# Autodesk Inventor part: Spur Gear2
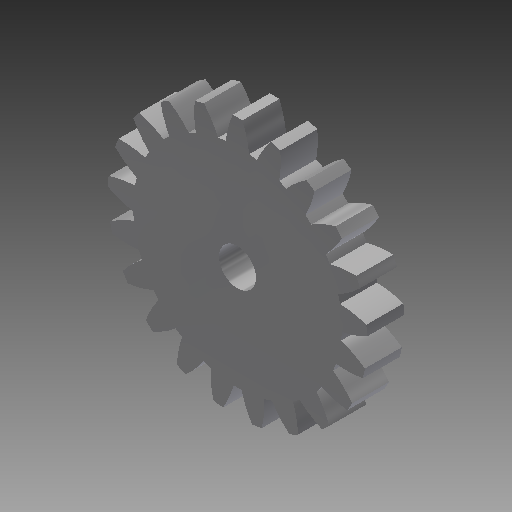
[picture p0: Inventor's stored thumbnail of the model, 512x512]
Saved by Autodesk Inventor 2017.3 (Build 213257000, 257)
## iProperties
Created: 2020-03
Part Number: Spur Gear2
Material: Steel
Document SubType Name: Modeling
Designer: Tim_G
Categories: <?xml version="1.0" encoding="UTF-16"?> <MemberInstance><Categories><FamilyTemplate><FamilyTemplateParameter ValueType="xs:double" Id="1" ObjectReferenceKey="da
Density: 1 g/cm^3
Appearance: Steel
CustomPartVersion: 1
Author: Tim_G
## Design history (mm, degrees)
sketch "Sketch1"
  geometry: C1 r 17.514 at (0, 0)
  constraints: 1 centre point
  dimensions: "d0" = 35.02752 diameter of C1 (= da_da)
extrude "Extrusion1" new body sketch "Sketch1" distance "d1" = 5 (= da_b); taper "d2" = 0 deg
workplane "Work Plane2"
sketch "Sketch2"
  geometry: C1 r 17.514 at (0, 0) reference; C2 r 15.991 at (0, 0)
  constraints: 1 centre point, 1 coincident
  dimensions: "d3" = 31.98165 diameter of C2 (= da_dw)
feature "Pitch Diameter" sketch "Sketch2" dims "d4" = 10, "d5" = 0
workplane "Work Plane8"
workplane "Work Plane9"
feature "Spur Gear" dims "da_b" = 5, "da_d" = 31.98165, "da_aw" = 25.12844, "da_da" = 35.02752, "da_df" = 28.17431, "da_dw" = 31.98165, angle "da_beta" = 0 deg, "da_lefttooth" = 0, "da_righttooth" = 0
sketch "Sketch3"
  geometry: C1 r 2.5 at (0, 0); 1 further point
  constraints: 1 centre point, 1 coincident
  dimensions: "d49" = 5 diameter of C1
extrude "Extrusion2" cut sketch "Sketch3" distance "d50" = 5; taper "d51" = 0 deg
body "Solid1"
body "Srf1"
other parameters: "d16" = 25.12844 (= da_aw), "d17" = 0, "d34" = 1.496 (computed from da_z), "d39" = 0, "d41" = 0, "d43" = 25.12844 (= da_aw), "d46" = 25.12844 (= da_aw), "d47" = 0, "d48" = 0
